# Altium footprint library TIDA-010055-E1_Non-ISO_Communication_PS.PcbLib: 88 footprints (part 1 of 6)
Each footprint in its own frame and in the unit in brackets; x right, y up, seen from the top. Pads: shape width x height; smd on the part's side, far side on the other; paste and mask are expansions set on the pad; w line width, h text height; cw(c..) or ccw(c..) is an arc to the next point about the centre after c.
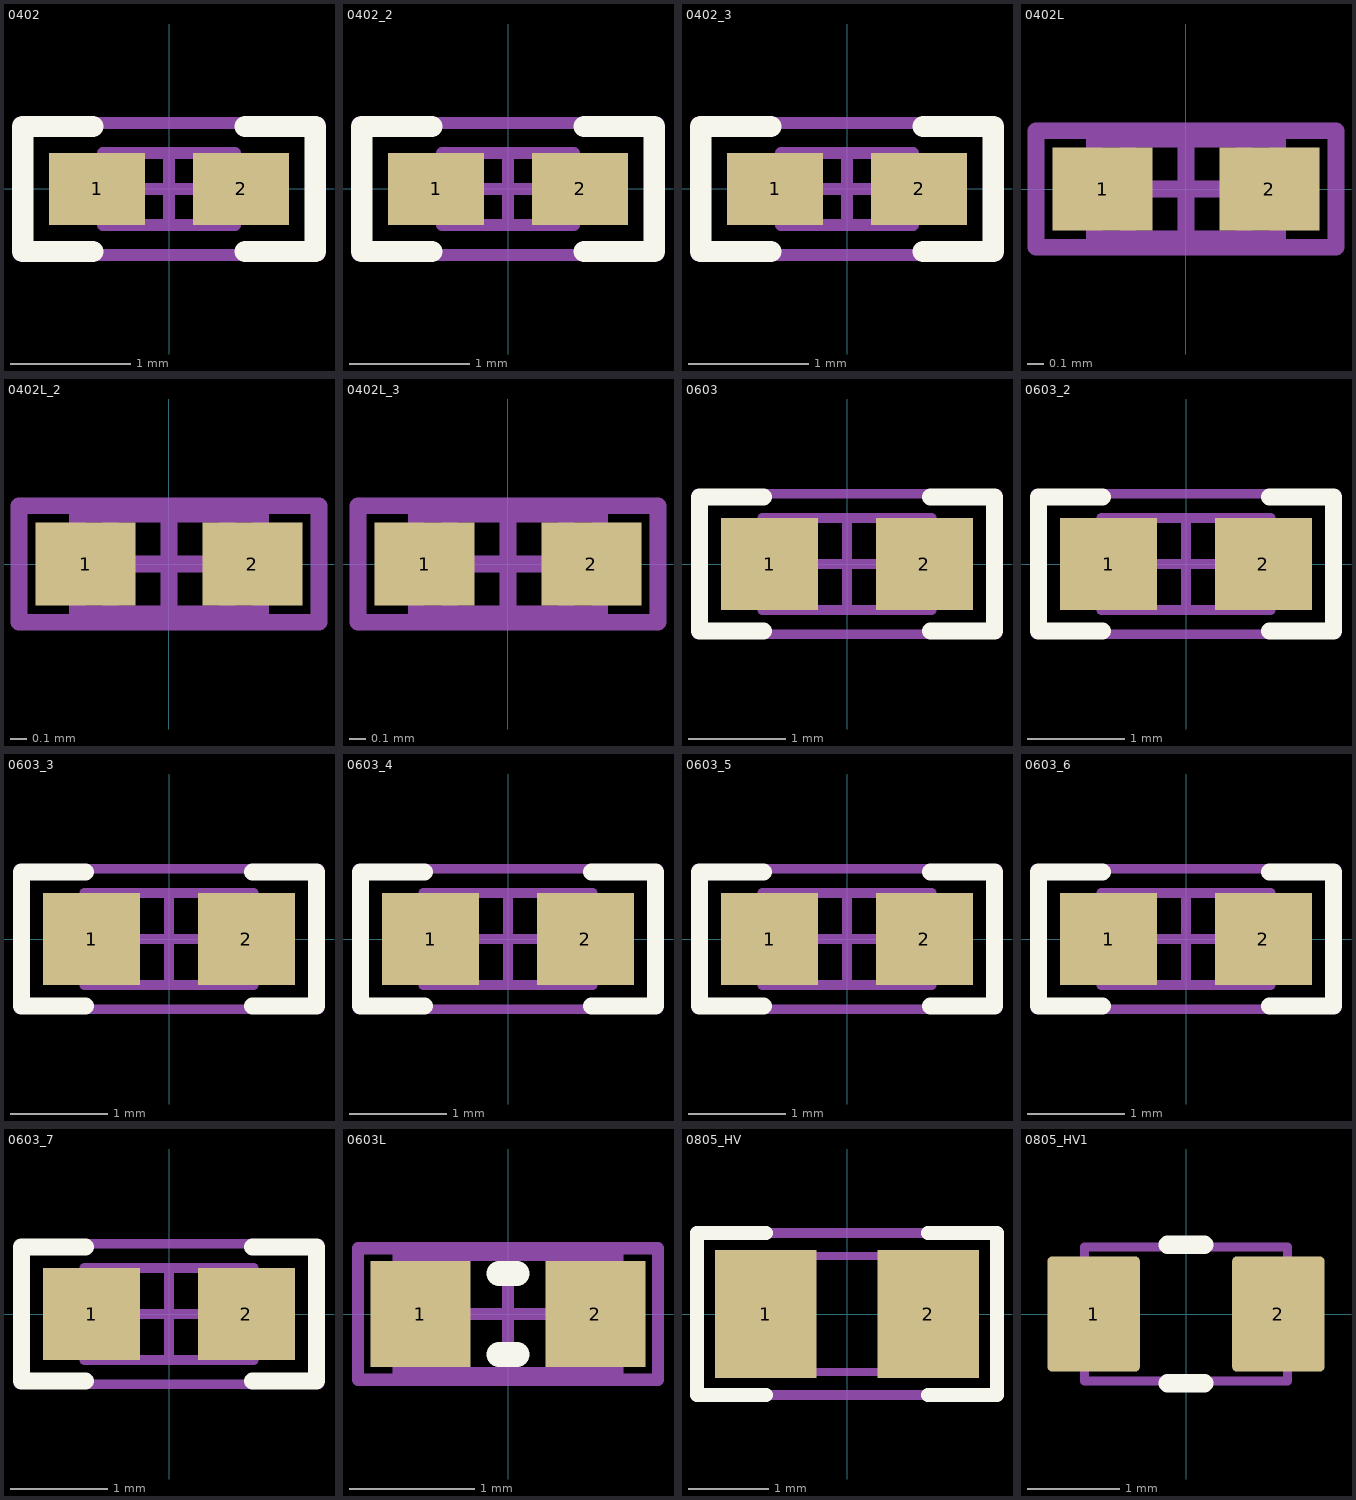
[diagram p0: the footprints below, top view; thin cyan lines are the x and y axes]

## 0402 [mm] "0402 from SM-752 data"
height 0.6
pads (2):
  rect 0.8x0.6 smd: 1(-0.6,0) 2(0.6,0)
Top Overlay:
  lines w0.178: -0.635,-0.521 -1.219,-0.521 -1.219,0.521 -0.635,0.521 ; 0.635,-0.521 1.219,-0.521 1.219,0.521 0.635,0.521
Mechanical 5:
  lines w0.1: -1.25,-0.55 1.25,-0.55 1.25,0.55 -1.25,0.55 -1.25,-0.55
  text ".Designator" at 0.898,0.341 h0.64
Mechanical 13:
  lines w0.1: -0.35,-0.3 -0.35,0.3 ; 0.35,-0.3 0.35,0.3 ; -0.55,-0.3 -0.55,0.3 0.55,0.3 0.55,-0.3 -0.55,-0.3
Mechanical 15:
  lines w0.1: -0.3,0 0.3,0 ; 0,-0.3 0,0.3 ; -1.25,-0.55 -1.25,0.55 1.25,0.55 1.25,-0.55 -1.25,-0.55
3D body: height 0.6, standoff 0, extent -0.549,-0.299 -0.351,0.299
3D body: height 0.6, standoff 0, extent -0.349,-0.299 0.349,0.299
3D body: height 0.6, standoff 0, extent 0.351,-0.299 0.549,0.299

## 0402_2 [mm]
pads (2):
  rect 0.8x0.6 smd: 1(-0.6,0) 2(0.6,0)
Top Overlay:
  lines w0.178: -0.635,-0.521 -1.219,-0.521 -1.219,0.521 -0.635,0.521 ; 0.635,-0.521 1.219,-0.521 1.219,0.521 0.635,0.521
Mechanical 5:
  lines w0.1: -1.25,-0.55 1.25,-0.55 1.25,0.55 -1.25,0.55 -1.25,-0.55
  text ".Designator" at 0.873,0.33 h0.64
Mechanical 13:
  lines w0.1: -0.35,-0.3 -0.35,0.3 ; 0.35,-0.3 0.35,0.3 ; -0.55,-0.3 0.55,-0.3 0.55,0.3 -0.55,0.3 -0.55,-0.3
Mechanical 15:
  lines w0.1: -0.3,0 0.3,0 ; 0,-0.3 0,0.3 ; -1.25,-0.55 1.25,-0.55 1.25,0.55 -1.25,0.55 -1.25,-0.55
3D body: height 0.6, standoff 0, extent 0.351,-0.299 0.549,0.299
3D body: height 0.6, standoff 0, extent -0.349,-0.299 0.349,0.299
3D body: height 0.6, standoff 0, extent -0.549,-0.299 -0.351,0.299

## 0402_3 [mm]
pads (2):
  rect 0.8x0.6 smd: 1(-0.6,0) 2(0.6,0)
Top Overlay:
  lines w0.178: -0.635,-0.521 -1.219,-0.521 -1.219,0.521 -0.635,0.521 ; 0.635,-0.521 1.219,-0.521 1.219,0.521 0.635,0.521
Mechanical 5:
  lines w0.1: -1.25,-0.55 -1.25,0.55 1.25,0.55 1.25,-0.55 -1.25,-0.55
  text ".Designator" at -1.051,-0.33 h0.64
Mechanical 13:
  lines w0.1: -0.35,-0.3 -0.35,0.3 ; 0.35,-0.3 0.35,0.3 ; -0.55,-0.3 -0.55,0.3 0.55,0.3 0.55,-0.3 -0.55,-0.3
Mechanical 15:
  lines w0.1: -0.3,0 0.3,0 ; 0,-0.3 0,0.3 ; -1.25,-0.55 -1.25,0.55 1.25,0.55 1.25,-0.55 -1.25,-0.55
3D body: height 0.6, standoff 0, extent -0.549,-0.299 -0.351,0.299
3D body: height 0.6, standoff 0, extent -0.349,-0.299 0.349,0.299
3D body: height 0.6, standoff 0, extent 0.351,-0.299 0.549,0.299

## 0402L [mm] "0402 from SM-752 data"
height 0.6
pads (2):
  rect 0.6x0.5 smd: 1(-0.5,0) 2(0.5,0)
Mechanical 5:
  lines w0.1: -0.9,-0.35 -0.9,0.35 0.9,0.35 0.9,-0.35 -0.9,-0.35
  text ".Designator" at -0.809,0.619 h0.64
Mechanical 13:
  lines w0.1: -0.35,-0.3 -0.35,0.3 ; 0.35,-0.3 0.35,0.3 ; -0.55,-0.3 0.55,-0.3 0.55,0.3 -0.55,0.3 -0.55,-0.3
Mechanical 15:
  lines w0.1: -0.3,0 0.3,0 ; 0,-0.3 0,0.3 ; -0.9,-0.35 0.9,-0.35 0.9,0.35 -0.9,0.35 -0.9,-0.35
3D body: height 0.6, standoff 0, extent 0.351,-0.299 0.549,0.299
3D body: height 0.6, standoff 0, extent -0.349,-0.299 0.349,0.299
3D body: height 0.6, standoff 0, extent -0.549,-0.299 -0.351,0.299

## 0402L_2 [mm]
pads (2):
  rect 0.6x0.5 smd: 1(-0.5,0) 2(0.5,0)
Mechanical 5:
  lines w0.1: -0.9,-0.35 -0.9,0.35 0.9,0.35 0.9,-0.35 -0.9,-0.35
  text ".Designator" at 2.837,0.406 h0.64
Mechanical 13:
  lines w0.1: -0.35,-0.3 -0.35,0.3 ; 0.35,-0.3 0.35,0.3 ; -0.55,-0.3 0.55,-0.3 0.55,0.3 -0.55,0.3 -0.55,-0.3
Mechanical 15:
  lines w0.1: -0.3,0 0.3,0 ; 0,-0.3 0,0.3 ; -0.9,-0.35 0.9,-0.35 0.9,0.35 -0.9,0.35 -0.9,-0.35
3D body: height 0.6, standoff 0, extent 0.351,-0.299 0.549,0.299
3D body: height 0.6, standoff 0, extent -0.349,-0.299 0.349,0.299
3D body: height 0.6, standoff 0, extent -0.549,-0.299 -0.351,0.299

## 0402L_3 [mm]
pads (2):
  rect 0.6x0.5 smd: 1(-0.5,0) 2(0.5,0)
Mechanical 5:
  lines w0.1: -0.9,-0.35 -0.9,0.35 0.9,0.35 0.9,-0.35 -0.9,-0.35
  text ".Designator" at -2.786,-0.279 h0.64
Mechanical 13:
  lines w0.1: -0.35,-0.3 -0.35,0.3 ; 0.35,-0.3 0.35,0.3 ; -0.55,-0.3 0.55,-0.3 0.55,0.3 -0.55,0.3 -0.55,-0.3
Mechanical 15:
  lines w0.1: -0.3,0 0.3,0 ; 0,-0.3 0,0.3 ; -0.9,-0.35 0.9,-0.35 0.9,0.35 -0.9,0.35 -0.9,-0.35
3D body: height 0.6, standoff 0, extent 0.351,-0.299 0.549,0.299
3D body: height 0.6, standoff 0, extent -0.349,-0.299 0.349,0.299
3D body: height 0.6, standoff 0, extent -0.549,-0.299 -0.351,0.299

## 0603 [mm] "0603 from SM-752 data"
height 1
pads (2):
  rect 1x0.95 smd: 1(-0.8,0) 2(0.8,0)
Top Overlay:
  lines w0.178: -0.864,-0.691 -1.524,-0.691 -1.524,0.693 -0.864,0.693 ; 0.864,-0.691 1.524,-0.691 1.524,0.693 0.864,0.693
Mechanical 5:
  lines w0.1: -1.55,-0.725 -1.55,0.725 1.55,0.725 1.55,-0.725 -1.55,-0.725
  text ".Designator" at -0.905,-0.419 h0.64
Mechanical 13:
  lines w0.1: -0.55,-0.475 -0.55,0.475 ; 0.55,-0.475 0.55,0.475 ; -0.875,-0.475 0.875,-0.475 0.875,0.475 -0.875,0.475 -0.875,-0.475
Mechanical 15:
  lines w0.1: -0.475,0 0.475,0 ; 0,-0.475 0,0.475 ; -1.55,-0.725 1.55,-0.725 1.55,0.725 -1.55,0.725 -1.55,-0.725
3D body: height 1, standoff 0, extent -0.874,-0.474 -0.551,0.474
3D body: height 1, standoff 0, extent -0.549,-0.474 0.549,0.474
3D body: height 1, standoff 0, extent 0.551,-0.474 0.874,0.474

## 0603_2 [mm]
pads (2):
  rect 1x0.95 smd: 1(-0.8,0) 2(0.8,0)
Top Overlay:
  lines w0.178: -0.864,-0.691 -1.524,-0.691 -1.524,0.693 -0.864,0.693 ; 0.864,-0.691 1.524,-0.691 1.524,0.693 0.864,0.693
Mechanical 5:
  lines w0.1: -1.55,-0.725 1.55,-0.725 1.55,0.725 -1.55,0.725 -1.55,-0.725
  text ".Designator" at -0.876,-0.305 h0.64
Mechanical 13:
  lines w0.1: -0.55,-0.475 -0.55,0.475 ; 0.55,-0.475 0.55,0.475 ; -0.875,-0.475 -0.875,0.475 0.875,0.475 0.875,-0.475 -0.875,-0.475
Mechanical 15:
  lines w0.1: -0.475,0 0.475,0 ; 0,-0.475 0,0.475 ; -1.55,-0.725 -1.55,0.725 1.55,0.725 1.55,-0.725 -1.55,-0.725
3D body: height 1, standoff 0, extent 0.551,-0.474 0.874,0.474
3D body: height 1, standoff 0, extent -0.549,-0.474 0.549,0.474
3D body: height 1, standoff 0, extent -0.874,-0.474 -0.551,0.474

## 0603_3 [mm]
pads (2):
  rect 1x0.95 smd: 1(-0.8,0) 2(0.8,0)
Top Overlay:
  lines w0.178: -0.864,-0.691 -1.524,-0.691 -1.524,0.693 -0.864,0.693 ; 0.864,-0.691 1.524,-0.691 1.524,0.693 0.864,0.693
Mechanical 5:
  lines w0.1: -1.55,-0.725 1.55,-0.725 1.55,0.725 -1.55,0.725 -1.55,-0.725
  text ".Designator" at 0.889,0.178 h0.64
Mechanical 13:
  lines w0.1: -0.55,-0.475 -0.55,0.475 ; 0.55,-0.475 0.55,0.475 ; -0.875,-0.475 -0.875,0.475 0.875,0.475 0.875,-0.475 -0.875,-0.475
Mechanical 15:
  lines w0.1: -0.475,0 0.475,0 ; 0,-0.475 0,0.475 ; -1.55,-0.725 -1.55,0.725 1.55,0.725 1.55,-0.725 -1.55,-0.725
3D body: height 1, standoff 0, extent 0.551,-0.474 0.874,0.474
3D body: height 1, standoff 0, extent -0.549,-0.474 0.549,0.474
3D body: height 1, standoff 0, extent -0.874,-0.474 -0.551,0.474

## 0603_4 [mm]
pads (2):
  rect 1x0.95 smd: 1(-0.8,0) 2(0.8,0)
Top Overlay:
  lines w0.178: -0.864,-0.691 -1.524,-0.691 -1.524,0.693 -0.864,0.693 ; 0.864,-0.691 1.524,-0.691 1.524,0.693 0.864,0.693
Mechanical 5:
  lines w0.1: -1.55,-0.725 1.55,-0.725 1.55,0.725 -1.55,0.725 -1.55,-0.725
  text ".Designator" at 0.873,0.329 h0.64
Mechanical 13:
  lines w0.1: -0.55,-0.475 -0.55,0.475 ; 0.55,-0.475 0.55,0.475 ; -0.875,-0.475 -0.875,0.475 0.875,0.475 0.875,-0.475 -0.875,-0.475
Mechanical 15:
  lines w0.1: -0.475,0 0.475,0 ; 0,-0.475 0,0.475 ; -1.55,-0.725 -1.55,0.725 1.55,0.725 1.55,-0.725 -1.55,-0.725
3D body: height 1, standoff 0, extent 0.551,-0.474 0.874,0.474
3D body: height 1, standoff 0, extent -0.549,-0.474 0.549,0.474
3D body: height 1, standoff 0, extent -0.874,-0.474 -0.551,0.474

## 0603_5 [mm]
pads (2):
  rect 1x0.95 smd: 1(-0.8,0) 2(0.8,0)
Top Overlay:
  lines w0.178: -0.864,-0.691 -1.524,-0.691 -1.524,0.693 -0.864,0.693 ; 0.864,-0.691 1.524,-0.691 1.524,0.693 0.864,0.693
Mechanical 5:
  lines w0.1: -1.55,-0.725 -1.55,0.725 1.55,0.725 1.55,-0.725 -1.55,-0.725
  text ".Designator" at -1.016,-0.335 h0.64
Mechanical 13:
  lines w0.1: -0.55,-0.475 -0.55,0.475 ; 0.55,-0.475 0.55,0.475 ; -0.875,-0.475 0.875,-0.475 0.875,0.475 -0.875,0.475 -0.875,-0.475
Mechanical 15:
  lines w0.1: -0.475,0 0.475,0 ; 0,-0.475 0,0.475 ; -1.55,-0.725 1.55,-0.725 1.55,0.725 -1.55,0.725 -1.55,-0.725
3D body: height 1, standoff 0, extent -0.874,-0.474 -0.551,0.474
3D body: height 1, standoff 0, extent -0.549,-0.474 0.549,0.474
3D body: height 1, standoff 0, extent 0.551,-0.474 0.874,0.474

## 0603_6 [mm]
pads (2):
  rect 1x0.95 smd: 1(-0.8,0) 2(0.8,0)
Top Overlay:
  lines w0.178: -0.864,-0.691 -1.524,-0.691 -1.524,0.693 -0.864,0.693 ; 0.864,-0.691 1.524,-0.691 1.524,0.693 0.864,0.693
Mechanical 5:
  lines w0.1: -1.55,-0.725 -1.55,0.725 1.55,0.725 1.55,-0.725 -1.55,-0.725
  text ".Designator" at -0.774,-0.162 h0.64
Mechanical 13:
  lines w0.1: -0.55,-0.475 -0.55,0.475 ; 0.55,-0.475 0.55,0.475 ; -0.875,-0.475 0.875,-0.475 0.875,0.475 -0.875,0.475 -0.875,-0.475
Mechanical 15:
  lines w0.1: -0.475,0 0.475,0 ; 0,-0.475 0,0.475 ; -1.55,-0.725 1.55,-0.725 1.55,0.725 -1.55,0.725 -1.55,-0.725
3D body: height 1, standoff 0, extent -0.874,-0.474 -0.551,0.474
3D body: height 1, standoff 0, extent -0.549,-0.474 0.549,0.474
3D body: height 1, standoff 0, extent 0.551,-0.474 0.874,0.474

## 0603_7 [mm]
pads (2):
  rect 1x0.95 smd: 1(-0.8,0) 2(0.8,0)
Top Overlay:
  lines w0.178: -0.864,-0.691 -1.524,-0.691 -1.524,0.693 -0.864,0.693 ; 0.864,-0.691 1.524,-0.691 1.524,0.693 0.864,0.693
Mechanical 5:
  lines w0.1: -1.55,-0.725 -1.55,0.725 1.55,0.725 1.55,-0.725 -1.55,-0.725
  text ".Designator" at -0.9,-0.32 h0.64
Mechanical 13:
  lines w0.1: -0.55,-0.475 -0.55,0.475 ; 0.55,-0.475 0.55,0.475 ; -0.875,-0.475 0.875,-0.475 0.875,0.475 -0.875,0.475 -0.875,-0.475
Mechanical 15:
  lines w0.1: -0.475,0 0.475,0 ; 0,-0.475 0,0.475 ; -1.55,-0.725 1.55,-0.725 1.55,0.725 -1.55,0.725 -1.55,-0.725
3D body: height 1, standoff 0, extent -0.874,-0.474 -0.551,0.474
3D body: height 1, standoff 0, extent -0.549,-0.474 0.549,0.474
3D body: height 1, standoff 0, extent 0.551,-0.474 0.874,0.474

## 0603L [mm] "0603 from SM-752 data"
height 1
pads (2):
  rect 0.8x0.85 smd: 1(-0.7,0) 2(0.7,0)
Top Overlay:
  lines w0.2: -0.071,-0.325 0.071,-0.325 ; -0.071,0.325 0.071,0.325
Mechanical 5:
  lines w0.1: -1.2,-0.525 1.2,-0.525 1.2,0.525 -1.2,0.525 -1.2,-0.525
  text ".Designator" at -0.869,-0.328 h0.64
Mechanical 13:
  lines w0.1: -0.55,-0.475 -0.55,0.475 ; 0.55,-0.475 0.55,0.475 ; -0.875,-0.475 0.875,-0.475 0.875,0.475 -0.875,0.475 -0.875,-0.475
Mechanical 15:
  lines w0.1: -0.475,0 0.475,0 ; 0,-0.475 0,0.475 ; -1.2,-0.525 -1.2,0.525 1.2,0.525 1.2,-0.525 -1.2,-0.525
3D body: height 1, standoff 0, extent -0.874,-0.474 -0.551,0.474
3D body: height 1, standoff 0, extent -0.549,-0.474 0.549,0.474
3D body: height 1, standoff 0, extent 0.551,-0.474 0.874,0.474

## 0805_HV [mil] "0805 with 30mil clearance between pads"
height 57.09
pads (2):
  rect 50x63 smd: 1(-40,0) 2(40,0)
Top Overlay:
  lines w7: -40,-40 -74,-40 -74,0 -74,40 -40,40 ; 40,-40 74,-40 74,0 74,40 40,40
Mechanical 5:
  lines w5: -74,-40 74,-40 74,40 -74,40 -74,-40
  text ".Designator" at 34,12 h25
Mechanical 13:
  lines w3.94: -25.59,-28.54 -25.59,28.54 ; 25.59,-28.54 25.59,28.54 ; -43.31,-28.54 43.31,-28.54 43.31,28.54 -43.31,28.54 -43.31,-28.54
3D body: height 57.09, standoff 0, extent -43.29,-28.52 -25.61,28.52
3D body: height 57.09, standoff 0, extent -25.57,-28.52 25.57,28.52
3D body: height 57.09, standoff 0, extent 25.61,-28.52 43.29,28.52

## 0805_HV1 [mm] "Custom footprint based on analyzing multiple manufacturer recommendations"
height 1.45
pads (2):
  rrect10% 1x1.25 smd: 1(-1,0) 2(1,0)
Top Overlay:
  lines w0.2: -0.2,-0.75 0.2,-0.75 ; -0.2,0.75 0.2,0.75
Mechanical 5:
  lines w0.1: -1.1,-0.725 -1.1,0.725 1.1,0.725 1.1,-0.725 -1.1,-0.725
  text ".Designator" at -0.831,-0.229 h0.64
3D body "0805_CapMax.stp": height 1.45, standoff 0, extent -1.1,-0.725 1.1,0.725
